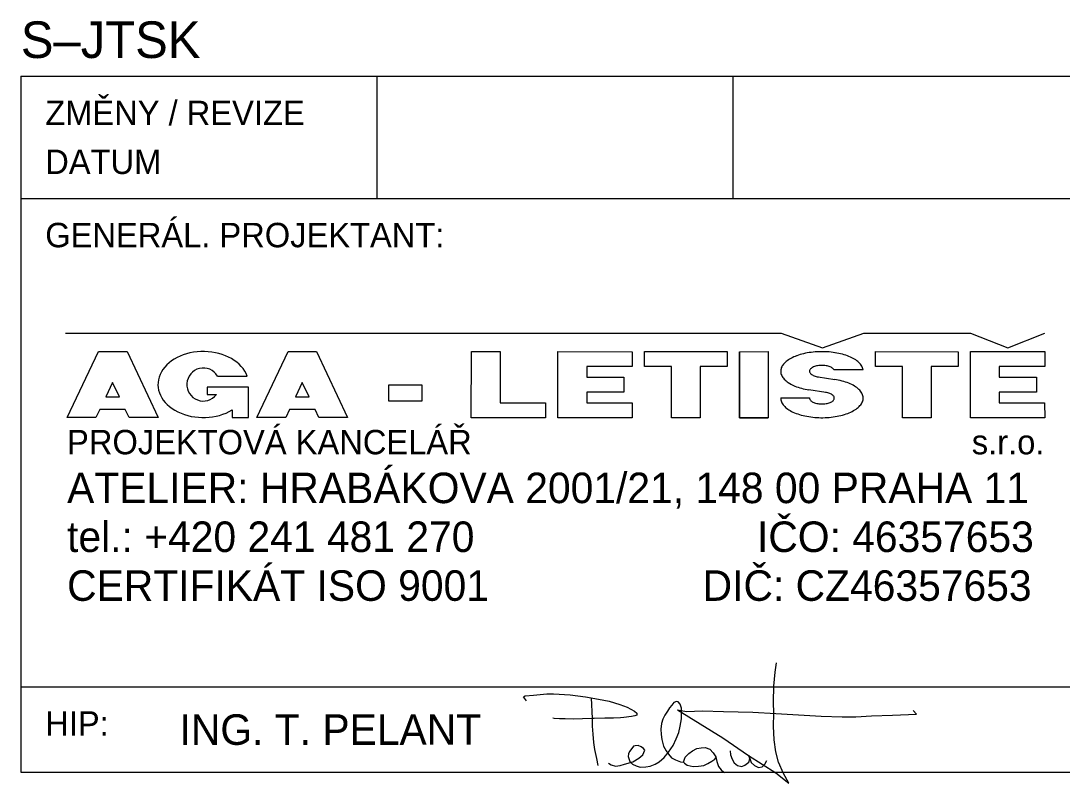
# Model space of a CAD drawing. Extents: x 210 to 654, y 0 to 297.
# Drawn here: x 437.5 to 522.8, y 86.1 to 148.5 of the extents above; entities that cross this region are included whole.
import ezdxf

# ---------------------------------------------------------------- set-up
doc = ezdxf.new("R2010")
doc.units = 0
doc.layers.add('AGA_Tisk Rozpiska', color=7, linetype='Continuous')

msp = doc.modelspace()

# ---------------------------------------------------------------- linework, layer by layer
at = {"layer": 'AGA_Tisk Rozpiska'}
for p, q in [((437.502, 143.999), (612.5, 143.999)), ((437.502, 143.999), (437.502, 133.999)), ((466.662, 143.999), (466.662, 133.999)), ((495.821, 143.999), (495.821, 133.999)), ((437.502, 133.999), (437.502, 86.999)), ((437.502, 133.999), (612.5, 133.999)), ((441.165, 122.954), (499.788, 122.954)), ((499.788, 122.954), (503.167, 121.757)), ((503.167, 121.757), (506.542, 122.954)), ((506.542, 122.954), (515.302, 122.954)), ((515.302, 122.954), (518.337, 121.757)), ((518.337, 121.757), (521.369, 122.954)), ((453.613, 119.446), (456.044, 119.446)), ((456.164, 118.541), (452.774, 118.541)), ((452.774, 118.541), (452.774, 117.933)), ((452.774, 117.933), (453.52, 117.933)), ((456.164, 116.046), (456.164, 118.541)), ((454.821, 116.677), (454.821, 116.046)), ((454.821, 116.046), (456.164, 116.046)), ((499.298, 95.199), (499.413, 95.963)), ((499.172, 94.063), (499.298, 95.199)), ((437.502, 93.999), (612.5, 93.999)), ((499.148, 92.769), (499.172, 94.063)), ((478.69, 93.175), (478.813, 93.276)), ((478.934, 92.84), (478.69, 93.175)), ((478.813, 93.276), (479.492, 93.322)), ((479.492, 93.322), (480.593, 93.433)), ((480.593, 93.433), (481.128, 93.433)), ((481.128, 93.433), (482.501, 93.341)), ((482.501, 93.341), (483.748, 93.186)), ((483.748, 93.186), (484.832, 92.999)), ((484.219, 93.104), (484.294, 91.393)), ((484.832, 92.999), (485.694, 92.818)), ((485.694, 92.818), (486.561, 92.545)), ((486.561, 92.545), (487.167, 92.326)), ((487.167, 92.326), (487.779, 92.017)), ((490.626, 92.283), (490.459, 92.014)), ((490.814, 92.499), (490.626, 92.283)), ((491.003, 92.716), (490.814, 92.499)), ((491.201, 92.803), (491.003, 92.716)), ((491.351, 92.758), (491.201, 92.803)), ((491.29, 92.126), (493.14, 90.977)), ((491.29, 92.126), (492.021, 91.972)), ((491.51, 92.583), (491.351, 92.758)), ((491.606, 92.258), (491.51, 92.583)), ((491.627, 91.946), (491.606, 92.258)), ((499.175, 91.828), (499.148, 92.769)), ((481.192, 91.405), (481.08, 91.434)), ((481.618, 91.379), (481.192, 91.405)), ((482.08, 91.373), (481.618, 91.379)), ((482.782, 91.364), (482.08, 91.373)), ((483.501, 91.376), (482.782, 91.364)), ((484.294, 91.393), (483.501, 91.376)), ((484.46, 91.404), (484.294, 91.393)), ((484.294, 91.393), (484.298, 90.784)), ((485.343, 91.446), (484.46, 91.404)), ((486.045, 91.438), (485.343, 91.446)), ((486.616, 91.458), (486.045, 91.438)), ((486.892, 91.477), (486.616, 91.458)), ((487.532, 91.576), (486.892, 91.477)), ((487.805, 91.631), (487.532, 91.576)), ((487.779, 92.017), (487.956, 91.845)), ((487.949, 91.677), (487.805, 91.631)), ((487.956, 91.845), (487.949, 91.677)), ((490.097, 91.362), (489.993, 91.004)), ((490.262, 91.667), (490.097, 91.362)), ((490.459, 92.014), (490.262, 91.667)), ((491.522, 90.774), (491.611, 91.371)), ((491.611, 91.371), (491.627, 91.946)), ((492.021, 91.972), (493.328, 92.023)), ((493.328, 92.023), (495.066, 91.993)), ((495.066, 91.993), (497.452, 91.915)), ((497.452, 91.915), (499.344, 91.803)), ((499.155, 90.773), (499.175, 91.828)), ((499.344, 91.803), (503.058, 91.611)), ((503.058, 91.611), (504.78, 91.542)), ((504.78, 91.542), (505.906, 91.544)), ((505.906, 91.544), (507.175, 91.63)), ((507.175, 91.63), (508.889, 91.673)), ((508.889, 91.673), (510.88, 91.771)), ((510.88, 91.771), (510.583, 92.064)), ((484.298, 90.784), (484.343, 90.121)), ((489.993, 91.004), (489.931, 90.537)), ((489.931, 90.537), (489.944, 90.094)), ((491.391, 90.248), (491.522, 90.774)), ((493.14, 90.977), (495.011, 89.81)), ((499.212, 89.651), (499.155, 90.773)), ((484.343, 90.121), (484.408, 89.443)), ((489.944, 90.094), (490.008, 89.693)), ((490.008, 89.693), (490.155, 89.148)), ((490.927, 89.201), (491.185, 89.753)), ((491.185, 89.753), (491.391, 90.248)), ((495.011, 89.81), (497.12, 88.382)), ((499.352, 88.681), (499.212, 89.651)), ((484.408, 89.443), (484.484, 88.875)), ((484.484, 88.875), (484.645, 88.128)), ((487.543, 88.952), (487.356, 88.7)), ((487.678, 89.128), (487.543, 88.952)), ((487.823, 89.175), (487.678, 89.128)), ((488.081, 89.192), (487.823, 89.175)), ((488.327, 89.098), (488.081, 89.192)), ((488.504, 88.944), (488.327, 89.098)), ((488.447, 88.422), (488.605, 88.803)), ((488.605, 88.803), (488.504, 88.944)), ((490.155, 89.148), (490.366, 88.756)), ((490.366, 88.756), (490.552, 88.474)), ((490.559, 88.64), (490.927, 89.201)), ((492.208, 88.548), (492.527, 88.755)), ((492.527, 88.755), (492.864, 88.962)), ((492.864, 88.962), (493.229, 89.006)), ((493.229, 89.006), (493.561, 89.028)), ((493.561, 89.028), (493.939, 88.887)), ((493.939, 88.887), (494.217, 88.592)), ((495.605, 88.754), (495.641, 88.435)), ((484.645, 88.128), (484.775, 87.565)), ((487.278, 88.51), (487.255, 88.287)), ((487.255, 88.287), (487.304, 88.124)), ((487.356, 88.7), (487.278, 88.51)), ((487.304, 88.124), (487.374, 87.888)), ((487.374, 87.888), (487.612, 87.664)), ((487.636, 87.851), (488.131, 88.162)), ((488.131, 88.162), (488.447, 88.422)), ((489.796, 87.849), (490.196, 88.209)), ((490.196, 88.209), (490.559, 88.64)), ((490.552, 88.474), (490.811, 88.195)), ((490.811, 88.195), (491.117, 88.031)), ((491.117, 88.031), (491.535, 87.856)), ((491.776, 87.836), (491.933, 88.252)), ((491.933, 88.252), (492.208, 88.548)), ((493.778, 87.731), (494.097, 87.919)), ((494.097, 87.919), (494.363, 88.085)), ((494.217, 88.592), (494.444, 88.257)), ((494.363, 88.085), (494.43, 88.182)), ((494.444, 88.257), (494.524, 87.892)), ((494.524, 87.892), (494.662, 87.477)), ((495.641, 88.435), (495.768, 88.064)), ((495.768, 88.064), (495.933, 87.783)), ((497.12, 88.382), (499.339, 86.962)), ((497.128, 87.82), (497.21, 88.104)), ((497.21, 88.104), (497.133, 88.39)), ((497.133, 88.39), (497.318, 87.804)), ((498.451, 87.675), (498.62, 87.98)), ((499.557, 87.827), (499.352, 88.681)), ((485.65, 87.735), (485.861, 87.619)), ((485.861, 87.619), (486.2, 87.513)), ((486.2, 87.513), (486.585, 87.558)), ((486.585, 87.558), (486.946, 87.675)), ((486.946, 87.675), (487.636, 87.851)), ((487.612, 87.664), (487.916, 87.537)), ((487.916, 87.537), (488.237, 87.429)), ((488.237, 87.429), (488.697, 87.442)), ((488.697, 87.442), (489.044, 87.503)), ((489.044, 87.503), (489.458, 87.659)), ((489.458, 87.659), (489.796, 87.849)), ((491.535, 87.856), (491.776, 87.836)), ((491.776, 87.836), (491.857, 87.748)), ((491.857, 87.748), (492.088, 87.598)), ((492.088, 87.598), (492.576, 87.483)), ((492.576, 87.483), (492.999, 87.512)), ((492.999, 87.512), (493.438, 87.561)), ((493.438, 87.561), (493.778, 87.731)), ((494.662, 87.477), (494.866, 87.195)), ((494.866, 87.195), (495.082, 87.006)), ((495.082, 87.006), (495.175, 86.994)), ((495.933, 87.783), (496.197, 87.553)), ((496.197, 87.553), (496.567, 87.475)), ((496.567, 87.475), (496.808, 87.579)), ((496.808, 87.579), (497.128, 87.82)), ((497.318, 87.804), (497.599, 87.545)), ((497.599, 87.545), (497.93, 87.393)), ((497.93, 87.393), (498.219, 87.441)), ((498.219, 87.441), (498.451, 87.675)), ((499.969, 86.912), (499.557, 87.827)), ((437.502, 86.999), (612.5, 86.999)), ((499.339, 86.962), (500.412, 86.11)), ((500.412, 86.11), (499.969, 86.912))]:
    msp.add_line(p, q, dxfattribs=at)
for points in [[(441.292, 116.046), (443.851, 121.451), (446.218, 121.451), (448.744, 116.046), (446.378, 116.046), (446.058, 116.718), (443.979, 116.718), (443.659, 116.046), (441.292, 116.046)], [(464.256, 116.046), (461.921, 116.046), (461.601, 116.718), (459.522, 116.718), (459.203, 116.046), (456.836, 116.046), (459.395, 121.451), (461.729, 121.451), (464.256, 116.046)], [(474.405, 121.449), (476.77, 121.449), (476.77, 117.261), (480.484, 117.261), (480.484, 116.043), (474.403, 116.041), (474.405, 121.449)], [(481.5, 116.043), (481.498, 121.449), (487.579, 121.447), (487.579, 120.232), (483.863, 120.232), (483.863, 119.356), (486.904, 119.356), (486.904, 118.138), (483.863, 118.14), (483.863, 117.261), (487.579, 117.261), (487.579, 116.043), (481.5, 116.043)], [(488.593, 121.449), (495.35, 121.449), (495.35, 120.232), (493.157, 120.232), (493.157, 116.043), (490.792, 116.043), (490.792, 120.232), (488.593, 120.232), (488.593, 121.449)], [(496.366, 121.447), (498.731, 121.449), (498.731, 116.043), (496.364, 116.043), (496.366, 121.447), (496.364, 116.043), (498.731, 116.043)], [(507.513, 121.449), (514.272, 121.447), (514.272, 120.232), (512.077, 120.232), (512.075, 116.041), (509.712, 116.041), (509.712, 120.232), (507.513, 120.232), (507.513, 121.449)], [(515.286, 116.043), (515.284, 121.449), (521.367, 121.451), (521.367, 120.232), (517.649, 120.232), (517.649, 119.354), (520.692, 119.354), (520.692, 118.138), (517.649, 118.138), (517.649, 117.261), (521.365, 117.259), (521.367, 116.043), (515.286, 116.043)], [(506.492, 119.96), (504.107, 119.96)], [(445.578, 117.741), (445.002, 118.925), (444.459, 117.741), (445.578, 117.741)], [(461.122, 117.741), (460.546, 118.925), (460.002, 117.741), (461.122, 117.741)], [(467.646, 118.746), (470.348, 118.744), (470.348, 117.393), (467.646, 117.395), (467.646, 118.746)], [(502.803, 119.388), (504.191, 119.168)], [(503.443, 118.104), (502.051, 118.324)], [(499.744, 117.661), (502.107, 117.661)]]:
    msp.add_lwpolyline(points, dxfattribs=at)
for centre, radius, start, end in [((502.727, 116.524), 4.884, 103.1816, 110.04967), ((503.003, 115.376), 6.065, 97.30642, 103.24881), ((503.11, 114.588), 6.861, 91.8822, 97.35488), ((503.122, 114.363), 7.086, 86.56733, 91.92311), ((503.151, 114.76), 6.688, 81.04263, 86.60944), ((503.301, 115.675), 5.76, 74.94415, 81.09507), ((503.63, 116.876), 4.515, 67.78121, 75.01936), ((500.704, 119.787), 0.97, 144.25082, 164.44486), ((501.133, 119.478), 1.498, 129.14586, 144.27143), ((501.701, 118.794), 2.387, 118.25363, 129.33649), ((502.271, 117.753), 3.574, 109.94733, 118.40964), ((503.005, 118.851), 1.465, 103.11962, 110.1043), ((503.088, 118.504), 1.822, 97.15251, 103.18963), ((503.119, 118.27), 2.058, 91.63876, 97.20294), ((503.122, 118.21), 2.118, 86.22243, 91.68157), ((503.132, 118.342), 1.986, 80.56797, 86.26698), ((503.182, 118.629), 1.694, 74.28757, 80.62427), ((504.127, 118.076), 3.217, 58.81739, 67.89713), ((504.71, 119.027), 2.101, 46.91897, 58.98921), ((505.252, 119.601), 1.312, 30.57505, 47.09565), ((452.45, 118.758), 1.351, 30.5964, 322.3836), ((500.52, 119.845), 0.776, 164.95884, 188.34837), ((500.624, 119.87), 0.883, 188.99094, 210.47116), ((500.993, 120.09), 1.312, 210.57497, 227.09559), ((502.342, 119.845), 0.234, 166.47774, 190.20237), ((502.381, 119.855), 0.273, 190.83645, 212.22461), ((502.393, 119.83), 0.287, 145.17228, 165.91047), ((502.499, 119.93), 0.414, 212.28803, 228.53724), ((502.52, 119.741), 0.442, 129.61837, 145.17159), ((502.667, 120.117), 0.665, 228.3469, 240.18492), ((502.692, 119.538), 0.708, 118.46387, 129.81483), ((502.843, 120.418), 1.014, 240.01314, 248.94518), ((502.866, 119.223), 1.067, 109.99726, 118.62744), ((502.988, 120.787), 1.41, 248.83132, 255.99518), ((503.08, 121.143), 1.778, 255.92123, 262.0575), ((503.287, 118.996), 1.312, 66.85072, 74.36944), ((503.443, 119.355), 0.921, 57.45238, 66.97771), ((503.621, 119.631), 0.593, 44.855, 57.63758), ((503.78, 119.788), 0.369, 27.48513, 45.02117), ((505.62, 119.82), 0.883, 8.99103, 30.47124), ((501.534, 120.663), 2.101, 226.91891, 238.98917), ((502.118, 121.615), 3.217, 238.81735, 247.8971), ((502.615, 122.814), 4.515, 247.78118, 255.01934), ((503.287, 113.412), 5.826, 75.26699, 81.50335), ((503.614, 114.63), 4.565, 68.00433, 75.34566), ((504.118, 115.859), 3.237, 58.88812, 68.1265), ((504.713, 116.833), 2.095, 46.71816, 59.0709), ((502.944, 124.015), 5.76, 254.94412, 261.09505), ((503.164, 116.343), 1.783, 76.11275, 82.05849), ((503.251, 116.687), 1.428, 69.28291, 76.17956), ((503.389, 117.047), 1.043, 60.87282, 69.38435), ((503.558, 117.348), 0.697, 49.88856, 61.02536), ((503.725, 117.543), 0.44, 34.93811, 50.0685), ((503.849, 117.63), 0.289, 14.90785, 34.94226), ((505.264, 117.412), 1.296, 29.88717, 46.90424), ((505.631, 117.625), 0.872, 7.61525, 29.75497), ((505.72, 117.647), 0.781, 343.10101, 6.91222), ((500.549, 117.65), 0.806, 179.25714, 202.57388), ((500.829, 117.774), 1.112, 202.9145, 221.75689), ((501.332, 118.218), 1.783, 221.62546, 235.3859), ((502.347, 117.647), 0.238, 176.70493, 199.4376), ((502.417, 117.674), 0.314, 199.82165, 218.78124), ((502.554, 117.783), 0.489, 218.70538, 232.81942), ((502.725, 118.004), 0.768, 232.6374, 243.07723), ((502.89, 118.323), 1.128, 242.93682, 251.01353), ((503.018, 118.687), 1.513, 250.92146, 257.55712), ((503.093, 119.016), 1.851, 257.49571, 263.2957), ((503.12, 119.232), 2.068, 263.25049, 268.63538), ((503.122, 119.28), 2.117, 268.59634, 273.89888), ((503.133, 119.149), 1.984, 273.858, 279.39398), ((503.18, 118.87), 1.702, 279.34257, 285.47627), ((503.281, 118.515), 1.332, 285.40252, 292.62739), ((503.429, 118.163), 0.951, 292.51445, 301.56787), ((503.602, 117.886), 0.624, 301.40262, 313.39653), ((503.761, 117.718), 0.393, 313.23021, 329.55484), ((503.87, 117.654), 0.267, 329.65563, 350.77503), ((503.902, 117.646), 0.234, 351.38303, 14.40503), ((505.051, 118.07), 1.58, 307.58041, 322.49265), ((505.509, 117.72), 1.004, 322.43391, 342.60142), ((501.929, 119.065), 2.819, 235.18698, 245.31838), ((502.477, 120.233), 4.109, 245.17654, 253.05299), ((502.869, 121.489), 5.425, 252.9621, 259.50345), ((503.069, 122.531), 6.486, 259.44237, 265.24713), ((503.121, 123.087), 7.044, 265.20041, 270.69352), ((503.127, 123.005), 6.963, 270.65037, 276.1865), ((503.208, 122.309), 6.261, 276.13734, 282.08073), ((503.455, 121.185), 5.11, 282.01394, 288.82149), ((503.892, 119.923), 3.776, 288.72003, 297.05453), ((504.464, 118.819), 2.532, 296.8972, 307.78424)]:
    msp.add_arc(centre, radius, start, end, dxfattribs=at)
msp.add_ellipse((452.45, 118.758), major_axis=(3.716, 0), ratio=0.727273, start_param=0.257331, end_param=5.404353, dxfattribs=at)

# ---------------------------------------------------------------- texts
for s, height, p in [('S–JTSK', 3, (437.502, 145.499)), ('ZMĚNY / REVIZE', 2, (439.502, 139.999)), ('DATUM', 2, (439.502, 135.999)), ('GENERÁL. PROJEKTANT:', 2, (439.502, 129.999)), ('ATELIER: HRABÁKOVA 2001/21, 148 00 PRAHA 11', 2.5, (441.292, 109.043)), ('tel.: +420 241 481 270', 2.5, (441.292, 105.043)), ('IČO: 46357653', 2.5, (497.803, 105.043)), ('CERTIFIKÁT ISO 9001', 2.5, (441.292, 101.043)), ('DIČ: CZ46357653', 2.5, (493.351, 101.043)), ('HIP:', 2, (439.502, 89.999))]:
    msp.add_text(s, height=height, dxfattribs=at).set_placement(p)
for s, height, rotation, p in [('PROJEKTOVÁ KANCELÁŘ', 2, 359.99972, (441.292, 113.043)), ('s.r.o.', 2, 359.99972, (515.401, 113.043)), ('ING. T. PELANT', 2.5, 0.0029, (450.502, 89.249))]:
    msp.add_text(s, height=height, rotation=rotation, dxfattribs=at).set_placement(p)

doc.saveas('drawing.dxf')
